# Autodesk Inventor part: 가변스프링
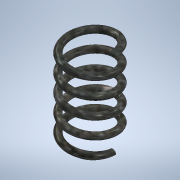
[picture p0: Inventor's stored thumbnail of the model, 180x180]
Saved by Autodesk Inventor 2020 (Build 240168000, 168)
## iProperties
Created: 2020-12
Part Number: 가변스프링
Material: 강철
Document SubType Name: Modeling
Designer: USER
Density: 7.85 g/cm^3
Appearance: 플레이트
Mass: 5.33411 g
Surface Area: 13.8246 cm^2
Volume: 0.679504 cm^3
Author: USER
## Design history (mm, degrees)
sketch "스케치1"
  geometry: L1 (0, 0)-(7, 0); L2 (7, 0)-(7, 26.5); L3 (7, 26.5)-(0, 26.5); L4 (0, 26.5)-(0, 0); C1 r 1 at (7, 0)
  constraints: 8 end point, 2 parallel, 1 centre point, 1 coincident, 1 horizontal, 1 perpendicular
  dimensions: "d0" = 14 diameter of L2 L4; "d1" = 26.5 distance of L1.end L2.end (derived); "d2" = 2 diameter of C1
feature "코일1" sketch "스케치1" pitch "d3" = 10; turns "d5" = 5; dims "d4" = 26.5 (= d1), "d6" = 0, angle "d7" = 90 deg, angle "d8" = 90 deg, "d9" = 0, "d10" = 0
sketch "스케치2"
  geometry: L1 (-6, 0)-(-8, 0) reference; L2 (-6, 0)-(-8, 0) reference; 1 further point
  constraints: 2 horizontal alignment
extrude "돌출1" cut sketch "스케치2" distance "d11" = 10; taper "d12" = 0 deg
node "작업 평면1"
sketch "스케치3"
  geometry: L1 (-1, 0)-(1, 0) reference; 1 further point
  constraints: 1 horizontal alignment
extrude "돌출2" cut sketch "스케치3" distance "d14" = 10; taper "d15" = 0 deg
node "솔리드1"
node "절단 모서리 투영1"
node "절단 모서리 투영2"
node "절단 모서리 투영3"
other parameters: "d13" = 90 deg
